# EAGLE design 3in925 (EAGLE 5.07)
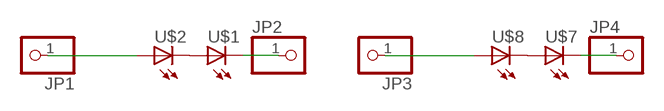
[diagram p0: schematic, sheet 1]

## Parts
JP1  PINHD-1X11X0.4  [1X01]
JP2  PINHD-1X11X0.4  [1X01]
JP3  PINHD-1X11X0.4  [1X01]
JP4  PINHD-1X11X0.4  [1X01]
U$1  LEDSMT1206  [1206]
U$2  LEDSMT1206  [1206]
U$7  LEDSMT1206  [1206]
U$8  LEDSMT1206  [1206]

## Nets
N$1: JP1.1 U$2.A
N$3: U$1.A U$2.C
N$4: JP2.1 U$1.C
N$5: JP3.1 U$8.A
N$6: U$7.A U$8.C
N$7: JP4.1 U$7.C

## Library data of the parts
JP1-JP4 = pinhead:PINHD-1X1: PIN HEADER
U$1 U$2 U$7 U$8 = led(2):LED: LED

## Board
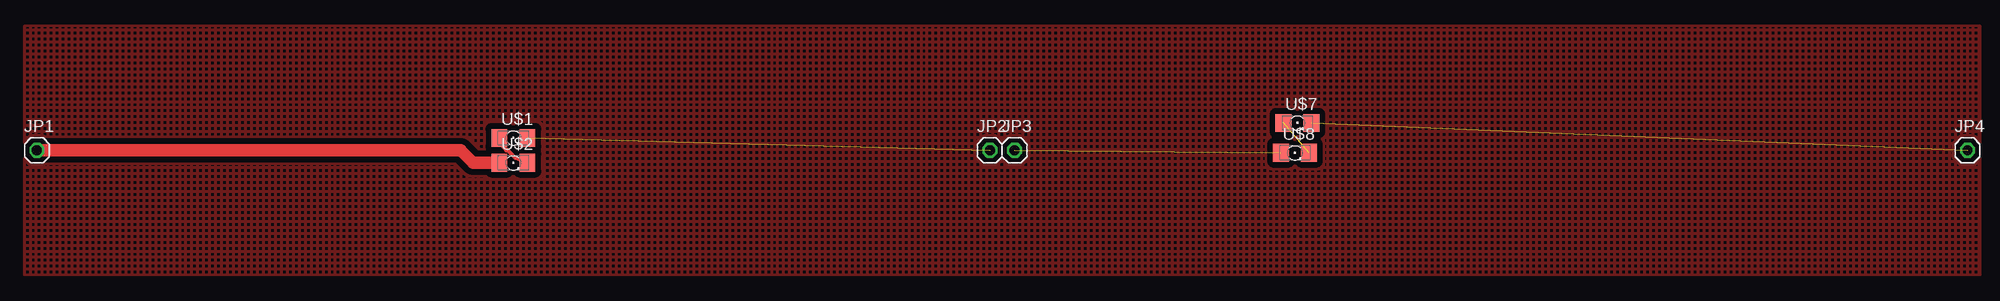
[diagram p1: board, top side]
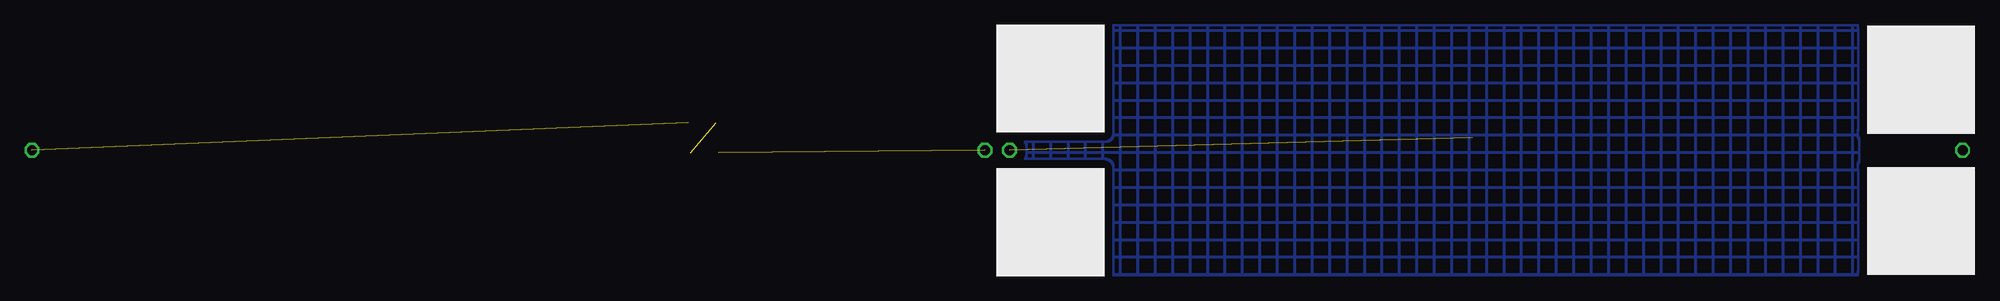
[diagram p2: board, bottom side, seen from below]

No outline drawn. Coordinates in mm, seen from the top.
Copper layers (1*16): Top 0.035mm / dielectric 1.5mm / Bottom 0.035mm
Design rules "default": minimum track width 10mil, minimum drill 24mil, track to track 8mil, track to pad 8mil, pad to pad 8mil, via to via 8mil, smd to smd 8mil, copper to edge 40mil, drill to drill 8mil, minimum pad ring 10mil, minimum via ring 8mil, stop-mask expansion 4mil, vias tented up to drill 0mil, thermal gap 10mil

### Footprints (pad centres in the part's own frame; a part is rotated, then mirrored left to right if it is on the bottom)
1X01 = drill 1.016 octagon: 1 0,0
1206 = smd 1.6 x 1.803: A -1.422,0; C 1.422,0

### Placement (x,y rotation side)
JP1  1.27,12.7 0 top
JP2  98.42,12.7 0 top
JP3  100.97,12.7 0 top
JP4  198.12,12.7 0 top
U$1  49.85,13.97 0 top
U$2  49.85,11.43 0 top
U$3  [SMD11]  5.5,19.9 0 bottom
U$4  [SMD11]  94.27,20.03 0 bottom
U$5  [SMD11]  5.5,5.5 0 bottom
U$6  [SMD11]  94.27,5.37 0 bottom
U$7  129.79,15.49 0 top
U$8  129.54,12.45 0 top

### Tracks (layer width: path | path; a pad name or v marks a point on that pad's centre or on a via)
N$1
  Top 1.27: JP1.1 44.45,12.7 45.72,11.43 U$2.A
N$2
  pour Top (isolate 0.61, hatched): 0,25.4 199.39,25.4 199.39,0 0,0
  pour Bottom (isolate 0.813, hatched): 11.81,25.4 99.69,25.4 99.69,0 11.81,0
N$3
  Top 0.406: U$1.A 47.88,13.97 49.15,12.7 49.28,12.7 50.04,11.94 50.19,11.94 U$2.C
N$4  (1 unrouted)
N$5  (1 unrouted)
N$6  (1 unrouted)
N$7  (1 unrouted)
